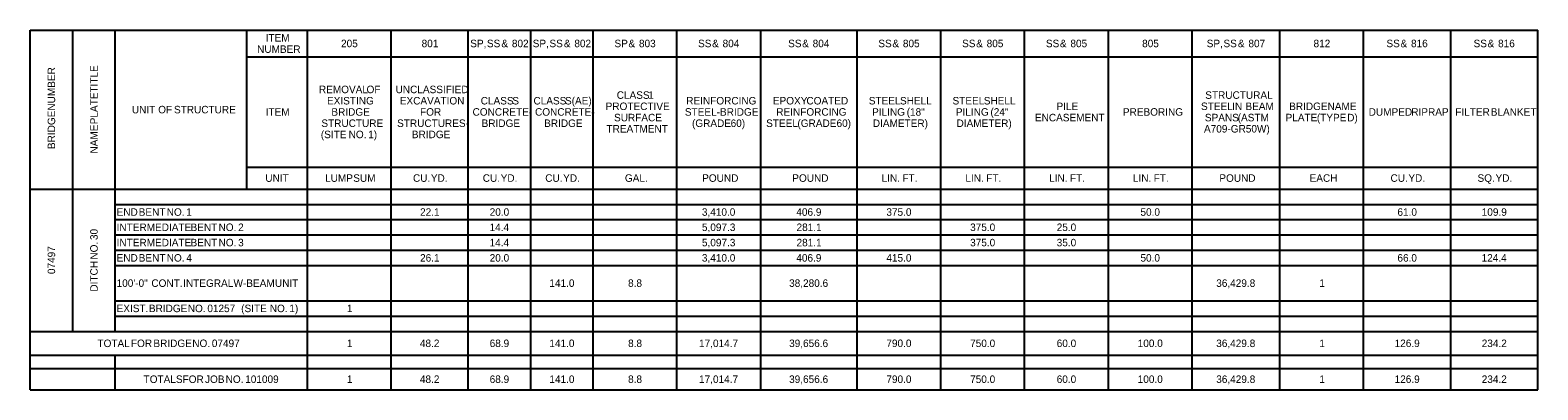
# Model space of a CAD drawing. Extents: x 192.8 to 249.4, y 129.2 to 148.9.
# Drawn here: x 224.27 to 249.4, y 138.16 to 144.15 of the extents above; entities that cross this region are included whole.
import ezdxf

# ---------------------------------------------------------------- set-up
doc = ezdxf.new("R2010")
doc.units = 0
doc.layers.add('B_Dimensions', color=7, linetype='Continuous')
doc.layers.add('B_Text', color=7, linetype='Continuous')

msp = doc.modelspace()

# ---------------------------------------------------------------- linework, layer by layer
at = {"layer": 'B_Dimensions'}
msp.add_line((224.27, 144.151), (224.27, 144.151), dxfattribs=at)
at = {"layer": 'B_Text'}
for p, q in [((224.27, 144.151), (249.399, 144.151)), ((224.27, 138.157), (224.27, 144.151)), ((224.979, 139.132), (224.979, 144.151)), ((225.688, 139.132), (225.688, 144.151)), ((227.882, 141.503), (227.882, 144.151)), ((228.89, 138.157), (228.89, 144.151)), ((230.287, 138.157), (230.287, 144.151)), ((231.572, 138.157), (231.572, 144.151)), ((232.613, 138.157), (232.613, 144.151)), ((233.655, 138.157), (233.655, 144.151)), ((235.051, 138.157), (235.051, 144.151)), ((236.447, 138.157), (236.447, 144.151)), ((238.054, 138.157), (238.054, 144.151)), ((239.45, 138.157), (239.45, 144.151)), ((240.846, 138.157), (240.846, 144.151)), ((242.242, 138.157), (242.242, 144.151)), ((243.638, 138.157), (243.638, 144.151)), ((245.1, 138.157), (245.1, 144.151)), ((246.496, 138.157), (246.496, 144.151)), ((247.948, 138.157), (247.948, 144.151)), ((249.399, 138.157), (249.399, 144.151)), ((227.882, 143.708), (249.399, 143.708)), ((227.882, 141.869), (249.399, 141.869)), ((224.27, 141.503), (249.399, 141.503)), ((225.688, 141.248), (249.399, 141.248)), ((225.688, 140.994), (249.399, 140.994)), ((225.688, 140.739), (249.399, 140.739)), ((225.688, 140.484), (249.399, 140.484)), ((225.688, 140.229), (249.399, 140.229)), ((225.688, 139.642), (249.399, 139.642)), ((225.688, 139.387), (249.399, 139.387)), ((224.27, 139.132), (249.399, 139.132)), ((224.27, 138.733), (249.399, 138.733)), ((225.688, 138.157), (225.688, 138.733)), ((224.27, 138.512), (249.399, 138.512)), ((224.27, 138.157), (249.399, 138.157))]:
    msp.add_line(p, q, dxfattribs=at)

# ---------------------------------------------------------------- texts
for s, p in [('ITEM', (228.196, 143.961)), ('205', (229.452, 143.867)), ('801', (230.795, 143.867)), ('SP,', (231.605, 143.867)), (' SS', (231.837, 143.867)), (' &', (232.078, 143.867)), (' 802', (232.253, 143.867)), ('SP,', (232.646, 143.867)), (' SS', (232.879, 143.867)), (' &', (233.12, 143.867)), (' 802', (233.294, 143.867)), ('SP', (234.009, 143.867)), (' &', (234.196, 143.867)), (' 803', (234.371, 143.867)), ('SS', (235.402, 143.867)), (' &', (235.59, 143.867)), (' 804', (235.765, 143.867)), ('SS', (236.904, 143.867)), (' &', (237.091, 143.867)), (' 804', (237.266, 143.867)), ('SS', (238.407, 143.867)), (' &', (238.595, 143.867)), (' 805', (238.77, 143.867)), ('SS', (239.803, 143.867)), (' &', (239.991, 143.867)), (' 805', (240.166, 143.867)), ('SS', (241.2, 143.867)), (' &', (241.387, 143.867)), (' 805', (241.562, 143.867)), ('805', (242.804, 143.867)), ('SP,', (243.88, 143.867)), (' SS', (244.113, 143.867)), (' &', (244.354, 143.867)), (' 807', (244.529, 143.867)), ('812', (245.661, 143.867)), ('SS', (246.876, 143.867)), (' &', (247.064, 143.867)), (' 816', (247.239, 143.867)), ('SS', (248.328, 143.867)), (' &', (248.515, 143.867)), (' 816', (248.69, 143.867)), ('NUMBER', (228.053, 143.773)), ('REMOVAL', (229.083, 143.101)), ('EXISTING', (229.218, 142.913)), (' OF', (229.831, 143.101)), ('UNCLASSIFIED', (230.361, 143.101)), ('EXCAVATION', (230.431, 142.913)), ('CLASS', (231.78, 142.913)), (' S', (232.26, 142.913)), ('CLASS', (232.659, 142.913)), (' S(AE)', (233.138, 142.913)), ('CLASS', (234.047, 143.007)), (' 1', (234.526, 143.007)), ('REINFORCING', (235.205, 142.913)), ('EPOXY', (236.649, 142.913)), (' COATED', (237.162, 142.913)), ('STEEL', (238.248, 142.913)), (' SHELL', (238.722, 142.913)), ('STEEL', (239.644, 142.913)), (' SHELL', (240.118, 142.913)), ('STRUCTURAL', (243.856, 143.007)), ('UNIT', (225.966, 142.765)), (' OF', (226.358, 142.765)), (' STRUCTURE', (226.621, 142.765)), ('ITEM', (228.196, 142.726)), ('BRIDGE', (229.291, 142.726)), ('FOR', (230.769, 142.726)), ('CONCRETE-', (231.644, 142.726)), ('CONCRETE-', (232.685, 142.726)), ('PROTECTIVE', (233.862, 142.82)), ('SURFACE', (234.002, 142.632)), ('STEEL-BRIDGE', (235.183, 142.726)), ('REINFORCING', (236.706, 142.726)), ('PILING', (238.303, 142.726)), (' (18"', (238.833, 142.726)), ('PILING', (239.699, 142.726)), (' (24"', (240.229, 142.726)), ('ENCASEMENT', (241.017, 142.632)), ('PILE', (241.376, 142.82)), ('PREBORING', (242.483, 142.726)), ('STEEL', (243.785, 142.82)), ('SPANS', (243.85, 142.632)), (' IN', (244.259, 142.82)), (' (ASTM', (244.35, 142.632)), (' BEAM', (244.479, 142.82)), ('PLATE', (245.195, 142.632)), ('BRIDGE', (245.254, 142.82)), (' (TYPE', (245.67, 142.632)), (' NAME', (245.848, 142.82)), (' D)', (246.175, 142.632)), ('DUMPED', (246.58, 142.726)), (' RIPRAP', (247.244, 142.726)), ('FILTER', (248.023, 142.726)), (' BLANKET', (248.568, 142.726)), ('STRUCTURE', (229.124, 142.538)), ('STRUCTURES-', (230.386, 142.538)), ('BRIDGE', (231.795, 142.538)), ('BRIDGE', (232.837, 142.538)), ('TREATMENT', (233.877, 142.445)), ('(GRADE', (235.301, 142.538)), (' 60)', (235.899, 142.538)), ('STEEL', (236.538, 142.538)), (' (GRADE', (237.012, 142.538)), (' 60)', (237.664, 142.538)), ('DIAMETER)', (238.315, 142.538)), ('DIAMETER)', (239.711, 142.538)), ('A709-GR50W)', (243.835, 142.445)), ('(SITE', (229.115, 142.351)), (' NO.', (229.532, 142.351)), (' 1)', (229.858, 142.351)), ('BRIDGE', (230.632, 142.351)), ('UNIT', (228.19, 141.624)), ('LUMP', (229.186, 141.624)), (' SUM', (229.609, 141.624)), ('CU.', (230.651, 141.624)), (' YD.', (230.902, 141.624)), ('CU.', (231.814, 141.624)), (' YD.', (232.066, 141.624)), ('CU.', (232.855, 141.624)), (' YD.', (233.107, 141.624)), ('GAL.', (234.183, 141.624)), ('POUND', (235.471, 141.624)), ('POUND', (236.973, 141.624)), ('LIN.', (238.462, 141.624)), (' FT.', (238.762, 141.624)), ('LIN.', (239.858, 141.624)), (' FT.', (240.158, 141.624)), ('LIN.', (241.254, 141.624)), (' FT.', (241.554, 141.624)), ('LIN.', (242.65, 141.624)), (' FT.', (242.95, 141.624)), ('POUND', (244.091, 141.624)), ('EACH', (245.595, 141.624)), ('CU.', (246.944, 141.624)), (' YD.', (247.195, 141.624)), ('SQ.', (248.394, 141.624)), (' YD.', (248.648, 141.624)), ('END', (225.711, 141.058)), (' BENT', (226.033, 141.058)), (' NO.', (226.5, 141.058)), (' 1', (226.826, 141.058)), ('22.1', (230.769, 141.058)), ('20.0', (231.929, 141.058)), ('3,410.0', (235.466, 141.058)), ('406.9', (237.04, 141.058)), ('375.0', (238.541, 141.058)), ('50.0', (242.776, 141.058)), ('61.0', (247.059, 141.058)), ('109.9', (248.464, 141.058)), ('INTERMEDIATE', (225.711, 140.804)), (' BENT', (226.897, 140.804)), (' NO.', (227.364, 140.804)), (' 2', (227.69, 140.804)), ('14.4', (231.928, 140.804)), ('5,097.3', (235.467, 140.804)), ('281.1', (237.044, 140.804)), ('375.0', (239.937, 140.804)), ('25.0', (241.38, 140.804)), ('INTERMEDIATE', (225.711, 140.549)), (' BENT', (226.897, 140.549)), (' NO.', (227.364, 140.549)), (' 3', (227.69, 140.549)), ('14.4', (231.928, 140.549)), ('5,097.3', (235.467, 140.549)), ('281.1', (237.044, 140.549)), ('375.0', (239.937, 140.549)), ('35.0', (241.38, 140.549)), ('END', (225.711, 140.294)), (' BENT', (226.033, 140.294)), (' NO.', (226.5, 140.294)), (' 4', (226.826, 140.294)), ('26.1', (230.769, 140.294)), ('20.0', (231.929, 140.294)), ('3,410.0', (235.466, 140.294)), ('406.9', (237.04, 140.294)), ('415.0', (238.541, 140.294)), ('50.0', (242.776, 140.294)), ('66.0', (247.059, 140.294)), ('124.4', (248.462, 140.294)), ('100\'-0"', (225.711, 139.873)), (' CONT.', (226.244, 139.873)), (' INTEGRAL', (226.774, 139.873)), (' W-BEAM', (227.613, 139.873)), (' UNIT', (228.304, 139.873)), ('141.0', (232.924, 139.873)), ('8.8', (234.236, 139.873)), ('38,280.6', (236.92, 139.873)), ('36,429.8', (244.039, 139.873)), ('1', (245.758, 139.873)), ('EXIST.', (225.711, 139.452)), (' BRIDGE', (226.203, 139.452)), (' NO.', (226.851, 139.452)), (' 01257', (227.177, 139.452)), ('  (SITE', (227.694, 139.452)), (' NO.', (228.218, 139.452)), (' 1)', (228.544, 139.452)), ('1', (229.549, 139.452)), ('TOTAL', (225.392, 138.87)), (' FOR', (225.903, 138.87)), (' BRIDGE', (226.278, 138.87)), (' NO.', (226.926, 138.87)), (' 07497', (227.252, 138.87)), ('1', (229.549, 138.87)), ('48.2', (230.766, 138.87)), ('68.9', (231.929, 138.87)), ('141.0', (232.924, 138.87)), ('8.8', (234.236, 138.87)), ('17,014.7', (235.419, 138.87)), ('39,656.6', (236.92, 138.87)), ('790.0', (238.541, 138.87)), ('750.0', (239.937, 138.87)), ('60.0', (241.38, 138.87)), ('100.0', (242.73, 138.87)), ('36,429.8', (244.039, 138.87)), ('1', (245.758, 138.87)), ('126.9', (247.012, 138.87)), ('234.2', (248.464, 138.87)), ('TOTALS', (226.161, 138.272)), (' FOR', (226.764, 138.272)), (' JOB', (227.138, 138.272)), (' NO.', (227.482, 138.272)), (' 101009', (227.808, 138.272)), ('1', (229.549, 138.272)), ('48.2', (230.766, 138.272)), ('68.9', (231.929, 138.272)), ('141.0', (232.924, 138.272)), ('8.8', (234.236, 138.272)), ('17,014.7', (235.419, 138.272)), ('39,656.6', (236.92, 138.272)), ('790.0', (238.541, 138.272)), ('750.0', (239.937, 138.272)), ('60.0', (241.38, 138.272)), ('100.0', (242.73, 138.272)), ('36,429.8', (244.039, 138.272)), ('1', (245.758, 138.272)), ('126.9', (247.012, 138.272)), ('234.2', (248.464, 138.272))]:
    msp.add_text(s, height=0.125, dxfattribs=at).set_placement(p)
for s, p in [(' NUMBER', (224.687, 142.764)), (' TITLE', (225.396, 143.065)), (' PLATE', (225.396, 142.536)), ('BRIDGE', (224.687, 142.17)), ('NAME', (225.396, 142.095)), (' 30', (225.396, 140.607)), ('07497', (224.687, 140.086)), (' NO.', (225.396, 140.281)), ('DITCH', (225.396, 139.794))]:
    msp.add_text(s, height=0.125, rotation=90, dxfattribs=at).set_placement(p)

doc.saveas('drawing.dxf')
